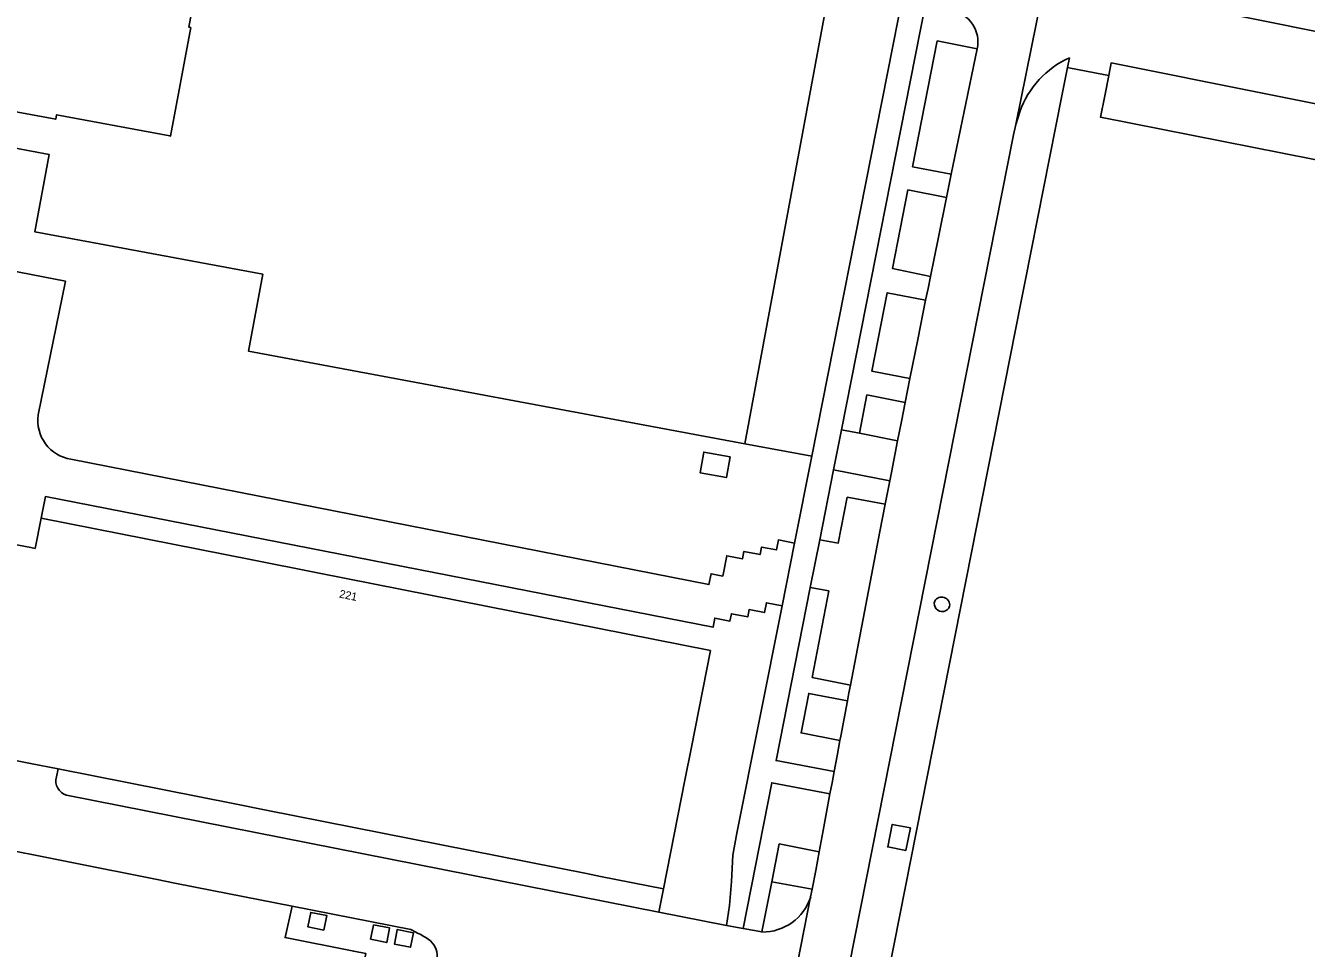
# Model space of a CAD drawing. Extents: x 158797 to 159887, y 384318 to 385255.
# Drawn here: x 159232.9 to 159393, y 384893.5 to 385008.8 of the extents above; entities that cross this region are included whole.
import ezdxf

# ---------------------------------------------------------------- set-up
doc = ezdxf.new("R2010")
doc.units = 0
for name, color, linetype in [('IMGEO_Lage_trafo', 7, 'Continuous'), ('IMGEO_Opslagtank', 7, 'Continuous'), ('IMGEO_Pand', 7, 'Continuous'), ('IMGEO_Pand_nummerreeks', 7, 'Continuous'), ('IMGEO_Parkeervlak_halfverhard', 7, 'Continuous'), ('IMGEO_Parkeervlak_open', 7, 'Continuous'), ('IMGEO_Rijbaan_lokaal_gesloten', 7, 'Continuous'), ('IMGEO_Rijbaan_lokaal_open', 7, 'Continuous'), ('IMGEO_Voetpad_open', 7, 'Continuous')]:
    doc.layers.add(name, color=color, linetype=linetype)

msp = doc.modelspace()

# ---------------------------------------------------------------- linework, layer by layer
at = {"layer": 'IMGEO_Lage_trafo'}
msp.add_lwpolyline([(159320.99, 384954.9), (159317.7, 384955.49), (159317.24, 384952.9), (159320.52, 384952.31), (159320.99, 384954.9)], dxfattribs=at)
at = {"layer": 'IMGEO_Opslagtank'}
for centre, radius, start, end in [((159347.42, 384936.35), 1.01, 353.1628, 148.5721), ((159347.49, 384936.55), 0.987, 160.844, 340.891)]:
    msp.add_arc(centre, radius, start, end, dxfattribs=at)
at = {"layer": 'IMGEO_Pand'}
for points in [[(159258.76, 385037.58), (159253.35, 385008.57), (159253.58, 385008.53), (159251.05, 384994.97), (159250.97, 384994.99), (159236.81, 384997.63), (159236.71, 384997.07), (159225.61, 384999.13), (159225.78, 385000), (159227.88, 385011.27), (159229.89, 385010.91), (159230.35, 385013.39), (159200.9, 385018.97), (159200.43, 385016.46), (159202.37, 385016.1), (159200.82, 385007.86), (159188.07, 385010.33), (159186.12, 385000), (159185.95, 384999.06)], [(159322.84, 384956.53), (159335.15, 385022.9), (159258.76, 385037.58)], [(159339.83, 384705.5), (159343.82, 384725.7), (159319.24, 384730.58), (159319.3, 384730.89), (159315.15, 384731.71), (159314.83, 384731.77), (159314.77, 384731.46), (159314.46, 384731.52), (159314.52, 384731.84), (159310.06, 384732.72), (159310, 384732.41), (159309.53, 384732.5), (159312.99, 384750), (159322.23, 384796.67), (159322.85, 384799.84), (159357.38, 384974.33), (159357.88, 384976.86), (159362.45, 385000), (159363.15, 385003.54)], [(159363.15, 385003.54), (159363.33, 385003.5), (159367.63, 385002.65), (159368.31, 385002.52)], [(159368.31, 385002.52), (159367.81, 385000), (159367.28, 384997.32), (159416.57, 384987.6)], [(159185.38, 384996.08), (159184.16, 384989.59), (159194.98, 384987.54), (159194.56, 384985.38), (159224.04, 384979.78), (159224.49, 384982.27), (159222.54, 384982.65), (159224.8, 384994.74), (159235.88, 384992.68), (159234.09, 384983.02), (159262.58, 384977.71), (159260.79, 384968.11), (159322.84, 384956.53)], [(159236.99, 384915.9), (159233.57, 384916.58), (159228.97, 384917.49), (159229.75, 384921.4), (159226.79, 384921.99), (159231.17, 384944.04), (159233.61, 384943.55), (159234.13, 384943.45), (159234.88, 384947.23)], [(159234.88, 384947.23), (159261.25, 384942.01), (159269.44, 384940.39), (159318.52, 384930.68), (159316.14, 384918.63), (159315.33, 384914.5), (159312.65, 384900.93)], [(159312.65, 384900.93), (159304.8, 384902.48), (159303.05, 384902.83), (159263.02, 384910.75), (159259.08, 384911.53), (159236.99, 384915.9)], [(159342.96, 384905.71), (159340.68, 384906.16), (159341.24, 384908.97), (159343.52, 384908.52), (159342.96, 384905.71)], [(159212.31, 384878.91), (159212.94, 384882.18), (159222.44, 384880.35), (159225.24, 384894.42), (159227.06, 384903.58), (159227.61, 384906.4), (159249.39, 384902.08), (159251.37, 384901.68), (159254.13, 384901.14), (159266.26, 384898.74)], [(159292.49, 384794.99), (159294.45, 384794.6), (159294.58, 384794.58), (159299.31, 384818.46), (159267.59, 384824.77), (159272.1, 384847.55), (159274.69, 384847.04), (159282, 384883.95), (159274.03, 384885.53), (159275.47, 384892.82), (159273.95, 384893.12), (159265.37, 384894.82), (159266.26, 384898.74)], [(159270.23, 384895.76), (159268.22, 384896.16), (159268.58, 384897.98), (159270.59, 384897.58), (159270.23, 384895.76)], [(159276.06, 384894.61), (159276.37, 384896.16), (159276.42, 384896.42), (159278.43, 384896.03), (159278.38, 384895.76), (159278.07, 384894.21), (159276.06, 384894.61)], [(159281.24, 384894.62), (159281.04, 384893.62), (159279.03, 384894.02), (159279.34, 384895.56), (159279.39, 384895.84), (159281.4, 384895.44), (159281.24, 384894.62)]]:
    msp.add_lwpolyline(points, dxfattribs=at)
at = {"layer": 'IMGEO_Parkeervlak_halfverhard'}
for points in [[(159337.15, 384957.84), (159334.9, 384958.28)], [(159322.84, 384956.53), (159331.19, 384954.97)], [(159340.94, 384951.89), (159333.9, 384953.26)]]:
    msp.add_lwpolyline(points, dxfattribs=at)
at = {"layer": 'IMGEO_Parkeervlak_open'}
for points in [[(159348.62, 384990.21), (159343.79, 384991.14), (159346.88, 385006.85), (159351.87, 385005.88)], [(159346.02, 384977.42), (159341.28, 384978.42), (159343.2, 384988.25), (159348.02, 384987.28)], [(159343.46, 384964.66), (159338.7, 384965.59), (159340.62, 384975.39), (159345.42, 384974.47)], [(159337.15, 384957.84), (159338.09, 384962.62), (159342.87, 384961.69)], [(159341.92, 384956.89), (159337.15, 384957.84)], [(159334.71, 384919.47), (159329.86, 384920.4), (159330.82, 384925.33), (159335.65, 384924.41)], [(159332.12, 384905.55), (159327.13, 384906.54), (159326.18, 384901.79)]]:
    msp.add_lwpolyline(points, dxfattribs=at)
at = {"layer": 'IMGEO_Rijbaan_lokaal_gesloten'}
for points in [[(159356.69, 384996.4), (159361.85, 385021.94)], [(159348.62, 384990.21), (159350.24, 384998.03), (159351.87, 385005.88)], [(159356.69, 384996.4), (159356.4, 384995.11), (159318.14, 384801.8), (159318.44, 384801.74), (159318.11, 384800.17), (159318.38, 384800.12), (159308.02, 384749.02), (159302.97, 384723.66), (159301.67, 384717.28)], [(159348.02, 384987.28), (159348.32, 384988.74), (159348.62, 384990.21)], [(159346.02, 384977.42), (159347.02, 384982.35), (159348.02, 384987.28)], [(159345.42, 384974.47), (159345.72, 384975.94), (159346.02, 384977.42)], [(159343.46, 384964.66), (159344.44, 384969.57), (159345.42, 384974.47)], [(159342.87, 384961.69), (159343.17, 384963.17), (159343.46, 384964.66)], [(159341.92, 384956.89), (159342.39, 384959.29), (159342.87, 384961.69)], [(159340.94, 384951.89), (159341.14, 384952.92), (159341.92, 384956.89)], [(159340.36, 384948.96), (159340.65, 384950.43), (159340.94, 384951.89)], [(159336.02, 384926.38), (159339.71, 384945.58), (159340.36, 384948.96)], [(159335.65, 384924.41), (159335.83, 384925.4), (159336.02, 384926.38)], [(159334.71, 384919.47), (159334.81, 384919.99), (159335.65, 384924.41)], [(159333.98, 384915.56), (159334.35, 384917.52), (159334.71, 384919.47)], [(159333.46, 384912.79), (159333.72, 384914.17), (159333.98, 384915.56)], [(159332.12, 384905.55), (159332.61, 384908.21), (159333.46, 384912.79)], [(159331.26, 384900.86), (159331.68, 384903.21), (159332.12, 384905.55)], [(159331.26, 384900.86), (159331.05, 384899.9)], [(159327.39, 384881.42), (159331.05, 384899.9)]]:
    msp.add_lwpolyline(points, dxfattribs=at)
msp.add_arc((159347.89, 385006.7), 4.07, 348.3994, 78.4392, dxfattribs=at)
at = {"layer": 'IMGEO_Rijbaan_lokaal_open'}
for points in [[(159365.26, 385013.85), (159381.41, 385010.62), (159432.72, 385000.28)], [(159363.15, 385003.54), (159363.39, 385004.76)], [(159415.63, 384994.72), (159387.5, 385000.31), (159368.61, 385004.1), (159368.31, 385002.52)], [(159357.2, 384998), (159356.69, 384996.4)], [(159234.52, 384960.15), (159237.91, 384976.85), (159230.85, 384978.2), (159229.29, 384970.28), (159229.08, 384969.75)], [(159329.05, 384944.11), (159327.03, 384944.51), (159326.78, 384943.26), (159324.92, 384943.62), (159324.74, 384942.67), (159322.72, 384943.07), (159322.53, 384942.14), (159320.56, 384942.53), (159320.06, 384939.99), (159318.6, 384940.28), (159318.34, 384938.93), (159238.61, 384954.58)], [(159234.88, 384947.23), (159235.41, 384949.92), (159318.85, 384933.61), (159319.07, 384934.74), (159320.97, 384934.37), (159321.15, 384935.29), (159323.18, 384934.89), (159323.36, 384935.81), (159325.28, 384935.43), (159325.52, 384936.67), (159327.49, 384936.29)], [(159327.49, 384936.29), (159329.05, 384944.11)], [(159236.78, 384914.9), (159236.99, 384915.9)], [(159312.07, 384898), (159238.06, 384912.61)], [(159266.26, 384898.74), (159281.08, 384895.83), (159281.72, 384895.5)], [(159320.53, 384896.33), (159312.07, 384898)], [(159322.61, 384895.96), (159320.53, 384896.33)], [(159324.97, 384895.53), (159322.61, 384895.96)]]:
    msp.add_lwpolyline(points, dxfattribs=at)
for centre, radius, start, end in [((159368.15, 384994.19), 11.59, 114.2229, 160.7992), ((159239.39, 384959.44), 4.92, 171.811, 260.8635), ((159238.6, 384914.41), 1.88, 164.9451, 253.5205), ((159325.04, 384901.84), 6.32, 269.3577, 342.0681), ((159277.98, 384887.12), 9.17, 54.8231, 65.9195), ((159281.9, 384892.56), 2.47, 355.5862, 56.3963)]:
    msp.add_arc(centre, radius, start, end, dxfattribs=at)
at = {"layer": 'IMGEO_Voetpad_open'}
for points in [[(159331.19, 384954.97), (159345.38, 385026.71)], [(159345.38, 385011.25), (159334.9, 384958.28)], [(159334.9, 384958.28), (159333.9, 384953.26)], [(159331.19, 384954.97), (159329.05, 384944.11)], [(159333.9, 384953.26), (159332.18, 384944.54)], [(159332.18, 384944.54), (159334.5, 384944.11), (159335.62, 384949.85), (159340.36, 384948.96)], [(159331, 384938.57), (159332.18, 384944.54)], [(159331, 384938.57), (159326.73, 384916.95), (159333.98, 384915.56)], [(159336.02, 384926.38), (159331.25, 384927.33), (159333.32, 384938.14), (159331, 384938.57)], [(159320.53, 384896.33), (159320.92, 384898.85), (159321.15, 384901.83), (159321.33, 384905.14), (159321.84, 384907.86), (159327.49, 384936.29)], [(159333.46, 384912.79), (159326.18, 384914.17), (159322.61, 384895.96)], [(159324.97, 384895.53), (159326.18, 384901.79)], [(159326.18, 384901.79), (159331.26, 384900.86)], [(159312.07, 384898), (159312.65, 384900.93)]]:
    msp.add_lwpolyline(points, dxfattribs=at)

# ---------------------------------------------------------------- texts
at = {"layer": 'IMGEO_Pand_nummerreeks'}
msp.add_text('221', height=1, rotation=348.6096, dxfattribs=at).set_placement((159272.08, 384937.32))

doc.saveas('drawing.dxf')
